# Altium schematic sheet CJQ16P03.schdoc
size 127 x 101 mm
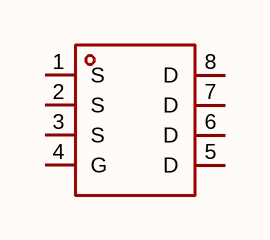
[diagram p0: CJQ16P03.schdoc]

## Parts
Q?  cjq16p03  [SOP-8_L5.0-W4.0-P1.27-LS6.2-BL]  (value not drawn)

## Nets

Not connected (* = marked no-connect by the designer): Q? 1(S) 2(S) 3(S) 4(G) 5(D) 6(D) 7(D) 8(D)

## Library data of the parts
Q? = cjq16p03: 数量:1个P沟道;漏源电压(Vdss):30V;连续漏极电流(Id):16A;导通电阻(RDS(on)):10mΩ@4.5V;耗散功率(Pd):3W;阈值电压(Vgs(th)):2.5V;; Manufacturer: CJ(江苏长电/长晶); AddInBom: yes; ModelId: a3315c1c78f949e6bb82c6eaca1c53c7; ModelName: SOP-8_L5.0-W4.0-H1.8-LS6.2-P1.27; ModelTransform: 244.094,196.85,0,90,0,0,0,0,0; Number: 1个P沟道; Drain to Source Voltage: 30V; Current - Continuous Drain(Id): 16A; Pd - Power Dissipation: 3W; Gate Threshold Voltage (Vgs(th)): 2.5V; Gate Charge(Qg): 100nC; Input Capacitance(Ciss): 5.9nF; Reverse Transfer Capacitance (Crss@Vds): 650pF; Type: P沟道; Output Capacitance(Coss): 900pF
